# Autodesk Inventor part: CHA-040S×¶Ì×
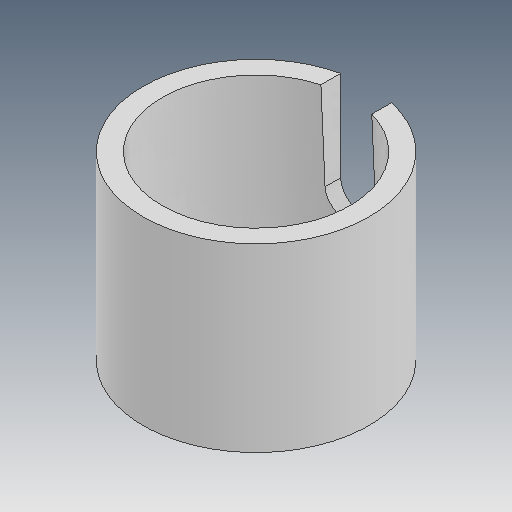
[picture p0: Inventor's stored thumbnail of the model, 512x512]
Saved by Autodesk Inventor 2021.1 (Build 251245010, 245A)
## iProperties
Created: 2019-12
Part Number: CHA-040S×¶Ì×
Material: Ogólny
Document SubType Name: Modeling
Designer: user
Density: 1 g/cm^3
Appearance: Domyślna
Author: user
Revision Number: ÈÎºÎ
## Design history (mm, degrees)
feature "ÊäÈë1"
node "Bryła1"
